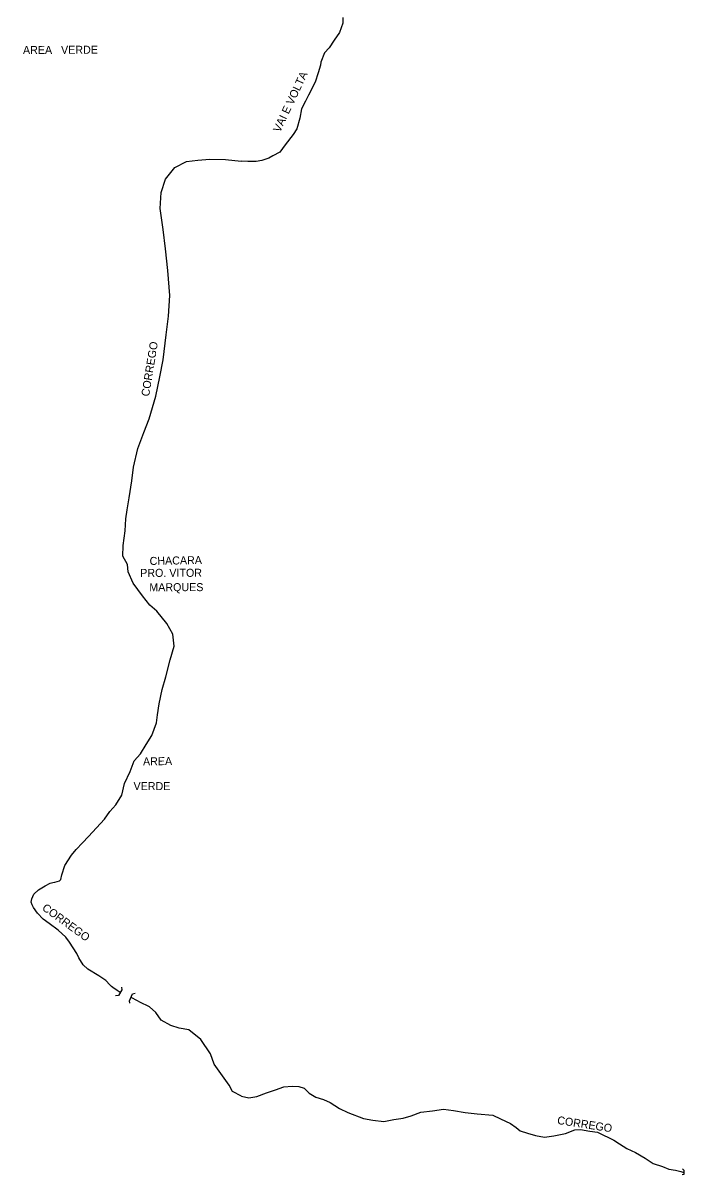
# Model space of a CAD drawing. Extents: x 325899 to 363134, y 7578590 to 7592502.
# Drawn here: x 337572 to 337903, y 7587352 to 7587928 of the extents above; entities that cross this region are included whole.
import ezdxf

# ---------------------------------------------------------------- set-up
doc = ezdxf.new("R2010")
doc.units = 0
for name, color, linetype in [('EDIFEXISTENT', 7, 'Continuous'), ('EDIFIDENTIF', 7, 'Continuous'), ('EDIFOBRAEXIS', 7, 'Continuous')]:
    doc.layers.add(name, color=color, linetype=linetype)

msp = doc.modelspace()

# ---------------------------------------------------------------- linework, layer by layer
at = {"layer": 'EDIFEXISTENT'}
for p, q in [((337621.53, 7587445.75), (337621.66, 7587444.4)), ((337620.02, 7587441.57), (337618.49, 7587441.38)), ((337621.66, 7587444.4), (337620.02, 7587441.57)), ((337625.46, 7587438.9), (337627, 7587442.32)), ((337627, 7587442.32), (337628.3, 7587442.77)), ((337625.69, 7587437.63), (337625.46, 7587438.9)), ((337901.95, 7587354.9), (337902.71, 7587354.25)), ((337902.69, 7587353.43), (337902.62, 7587352.05)), ((337902.71, 7587354.25), (337902.69, 7587353.43)), ((337902.62, 7587352.05), (337901.77, 7587351.82))]:
    msp.add_line(p, q, dxfattribs=at)
at = {"layer": 'EDIFOBRAEXIS'}
for points in [[(337732.14, 7587930.4), (337732.11, 7587927.54), (337730.53, 7587922.91), (337727.75, 7587918.98), (337725.29, 7587915.31), (337722.98, 7587912.76), (337721.14, 7587908.13), (337720.93, 7587906.61), (337719.77, 7587902.67), (337718.29, 7587898.04), (337714.92, 7587891.55), (337713.45, 7587888.65), (337711.53, 7587884.78), (337710.55, 7587880.08), (337709.12, 7587874.67), (337707.3, 7587871.86), (337703.21, 7587866.73), (337700.7, 7587863.11), (337697.17, 7587861.31), (337695.04, 7587860.14), (337691.68, 7587858.93), (337688.71, 7587858.46), (337684.65, 7587858.36), (337681.39, 7587858.55)], [(337591.66, 7587501.91), (337593.18, 7587506.54), (337596.38, 7587511.62), (337598.74, 7587514.5), (337601.99, 7587517.8), (337604.91, 7587521.01), (337608.93, 7587525.28), (337612.94, 7587529.74), (337615.69, 7587533.45), (337618.56, 7587536.78), (337621.55, 7587541.71), (337623.02, 7587547.5), (337625.72, 7587553.45), (337627.79, 7587558.83), (337630.99, 7587562.38), (337633.83, 7587566.93), (337636.67, 7587571.41), (337639, 7587577.82), (337639.45, 7587581.77), (337640.3, 7587587.34), (337641.83, 7587594.5), (337643.56, 7587600.85), (337645.8, 7587609.29), (337647.78, 7587616.09), (337647.16, 7587622.11), (337644.05, 7587627.42), (337639.15, 7587633.59), (337635.69, 7587636.66), (337632.03, 7587641.37), (337627.23, 7587647.64), (337624.78, 7587653.34), (337624.46, 7587657), (337622.09, 7587661.1), (337622.25, 7587666.53), (337623.23, 7587673.85), (337623.68, 7587679.83), (337624.23, 7587684.27), (337625.21, 7587690.34), (337626.64, 7587698.85), (337627.38, 7587705.59), (337629.69, 7587714.9), (337632.66, 7587722.87), (337635.33, 7587729.79), (337638.65, 7587741.11), (337640.58, 7587750.82), (337642.29, 7587759.33), (337643.73, 7587771.85), (337644.95, 7587781.17), (337645.59, 7587791.49), (337644.54, 7587803.92), (337643.42, 7587814.8), (337642.22, 7587824.39), (337640.82, 7587834.95), (337641.32, 7587842.84), (337643.38, 7587849.63), (337648.07, 7587855.35), (337653.88, 7587858.46), (337659.6, 7587859.13), (337665.54, 7587859.56), (337673.43, 7587859.33), (337678.05, 7587858.9), (337681.39, 7587858.55)], [(337620.86, 7587442.94), (337619.3, 7587443.95), (337617.04, 7587445.44), (337616.52, 7587445.97), (337615.58, 7587446.9), (337613.69, 7587448.95), (337610.05, 7587451.37), (337604.58, 7587454.64), (337602.23, 7587456.91), (337600.06, 7587460.28), (337599.13, 7587462.56), (337595.45, 7587468.17), (337593.58, 7587470.75), (337589.78, 7587474.13), (337585.3, 7587477.54), (337582.32, 7587479.73), (337579.49, 7587482.74), (337577.52, 7587485.44), (337576.78, 7587486.89), (337576.21, 7587488.26), (337576.66, 7587489.76), (337577.59, 7587492.2), (337580.01, 7587494.32), (337583.3, 7587496.26), (337585.81, 7587497.69), (337587.1, 7587498.08), (337588.12, 7587498.19), (337589.36, 7587498.5), (337590.5, 7587498.81), (337591.05, 7587499.47), (337591.66, 7587501.91)], [(337681.39, 7587391.16), (337676.96, 7587393.5), (337675.35, 7587396.74), (337671.9, 7587401.32), (337667.86, 7587407.19), (337665.93, 7587412.43), (337661.1, 7587419.56), (337655.08, 7587424.31), (337650.36, 7587425.22), (337646.19, 7587426.45), (337641.25, 7587429.19), (337638.57, 7587432.98), (337635.43, 7587435.94), (337630.7, 7587438.27), (337629.48, 7587438.82), (337626.3, 7587440.56)], [(337681.39, 7587391.16), (337685.13, 7587390.44), (337689.19, 7587390.96), (337693.98, 7587392.91), (337698.42, 7587394.45), (337702.56, 7587395.94), (337706.74, 7587396.22), (337710.12, 7587395.98), (337712.81, 7587395.27), (337715.34, 7587392.76), (337718.56, 7587390.62), (337722.54, 7587389.53), (337725.86, 7587388.05), (337730.4, 7587385.08), (337734.68, 7587383.09), (337742.44, 7587380.04), (337747.05, 7587379.27), (337752.58, 7587378.5), (337757.68, 7587379.56), (337762.35, 7587380.24), (337766.23, 7587381.43), (337771.15, 7587383.17), (337776.94, 7587383.8), (337782.52, 7587384.68), (337787.49, 7587383.96), (337793.35, 7587383.09), (337799.28, 7587382.3), (337807.07, 7587381.71), (337811.02, 7587379.8), (337815.91, 7587377.49), (337818.73, 7587375.48), (337820.88, 7587373.85), (337824.48, 7587372.76), (337828.54, 7587371.58), (337832.92, 7587370.79), (337837.57, 7587371.42), (337843.43, 7587372.53), (337848.1, 7587374.35), (337850.94, 7587374.6), (337855.65, 7587373.73), (337859.51, 7587373.22), (337862.55, 7587371.74), (337865.03, 7587370.57), (337867.7, 7587369.15), (337870.43, 7587367.45), (337874.18, 7587365.11), (337878.47, 7587363.05), (337883.26, 7587360.2), (337887.24, 7587357.61), (337892.03, 7587356.03), (337895.22, 7587354.73), (337898.49, 7587354.2), (337901.07, 7587353.61), (337902.66, 7587353.11)]]:
    msp.add_lwpolyline(points, dxfattribs=at)

# ---------------------------------------------------------------- texts
at = {"layer": 'EDIFIDENTIF'}
for s, rotation, p in [('AREA   VERDE', 0.26097, (337572.2, 7587912.13)), ('VAI E VOLTA', 64.70074, (337700.67, 7587872.65)), ('CORREGO', 80.6597, (337635.22, 7587740.77)), ('CHACARA', 1.15141, (337635.54, 7587656.71)), ('PRO. VITOR', 0.06832, (337630.8, 7587650.78)), ('MARQUES', 0.05528, (337635.35, 7587643.62)), ('AREA', 0.88002, (337632.22, 7587556.51)), ('VERDE', 359.79173, (337627.45, 7587544.23)), ('CORREGO', 324.04296, (337581.4, 7587484.56)), ('CORREGO', 351.27077, (337839.13, 7587377.33))]:
    msp.add_text(s, height=4, rotation=rotation, dxfattribs=at).set_placement(p)

doc.saveas('drawing.dxf')
